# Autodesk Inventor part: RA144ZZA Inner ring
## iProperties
Category: PARTsolutions
Created: 2011-07
Part Number: RA144ZZA Inner ring
Catalog Web Link: www.cadenas.de
Description: Six types ir - Inch system sizes
Document SubType Name: Modeling
Designer: PARTsolutions
Density: 1 g/cm^3
NB: RA144ZZA Inner ring
NN: Six types ir
NT: Inch system sizes
NBSYN: RA144ZZA Inner ring
LINA: RA144ZZA Inner ring
SD: 3.175
D: 6.350
B: 2.380
B1: 2.779
D1: 7.52
D2: 7.52
C1: 0.58
C2: 0.79
R: 0.08
ORDER: RA144ZZA
CR: 284
COR: 96
CRF: 29
CORF: 10
LSG: 59000
LSO: 70000
MASS: 0.27
ORDER1: R144
WSS: RA144ZA
WDS: RA144ZZA
UTWF: FLR144
FORSS: FLRA144ZA
FORDS: FLRA144ZZA
DA1: 3.9
DA2: 4
DA: 5.5
RAS: 0.08
MASS1: 0.33
VERS: 3
X: 1.587
N: 9
O: 14.954
RB: 0.470
KT: DUMMY
SUPPLIER: NTN
ARTICLENO: RA144ZZA Inner ring
BOMINFO: RA144ZZA Inner ring
CREATOR: CADENAS GmbH
PSOL_IDENT_0: {\\10.0.0.251\ps_data\23d-libs\ntn\ball_roller_bearings\miniature_extra_small_bb\inch_system_sizes\i
PSOL_IDENT_1: ss_ir.prj},189 {VTYP=3D},{NB=RA144ZZA Inner ring},{LINA=RA144ZZA Inner ring},{NN=Six types ir},{DATE
PSOL_IDENT_2: =11.12.2007 08:48:22},{GEOMDATE=28.06.2007 13:01:00},{VERSION=},{LINEID=16080},{LINESUBID=-1},{WBVAR
PSOL_IDENT_3: =}  {NB=RA144ZZA Inner ring},{LINA=RA144ZZA Inner ring},{KT=DUMMY},{IDNR=},{SD=3.175},{D=6.350},{B=2
PSOL_IDENT_4: .380},{B1=2.779},{D1=7.52},{D2=7.52},{C1=0.58},{C2=0.79},{R=0.08},{ORDER=RA144ZZA},{CR=284},{COR=96}
PSOL_IDENT_5: ,{CRF=29},{CORF=10},{LSG=59000},{LSO=70000},{MASS=0.27},{ORDER1=R144},{WSS=RA144ZA},{WDS=RA144ZZA},{
PSOL_IDENT_6: UTWF=FLR144},{FORSS=FLRA144ZA},{FORDS=FLRA144ZZA},{DA1=3.9},{DA2=4},{DA=5.5},{RAS=0.08},{MASS1=0.33}
PSOL_IDENT_7: ,{VERS=3},{X=1.5875},{N=9},{O=14.95425},{RB=0.4699}
Title: RA144ZZA Inner ring
Author: Cadenas PARTsolutions
Comments: Inch system sizes
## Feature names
1. Revolution1
